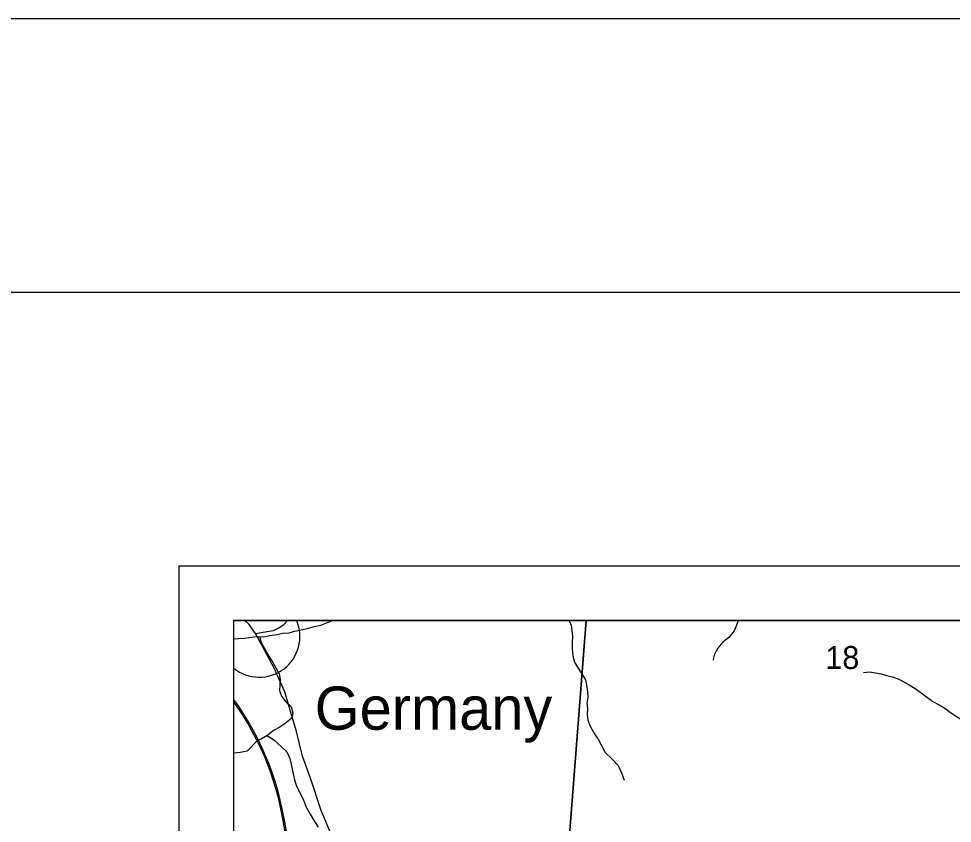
# Model space of a CAD drawing. Extents: x 0 to 40.8, y 0 to 22.
# Drawn here: x 1.707 to 3.414, y 20.53 to 22 of the extents above; entities that cross this region are included whole.
import ezdxf

# ---------------------------------------------------------------- set-up
doc = ezdxf.new("R2010")
doc.units = 0
for name, color, linetype in [('Default', 7, 'Continuous'), ('GM_X_County_Road', 7, 'Continuous'), ('GM_X_Minor_River', 7, 'Continuous'), ('GM_X_Rail_Line', 7, 'Continuous'), ('GM_X_Rail_Line_Text', 7, 'Continuous'), ('GM_X_Section_Text', 7, 'Continuous'), ('GM_X_Unincorporated_Location', 7, 'Continuous'), ('GM_X_Unincorporated_Text', 7, 'Continuous'), ('SH_Border', 7, 'Continuous'), ('SH_Cut_Line', 7, 'Continuous'), ('SH_Data', 7, 'Continuous')]:
    doc.layers.add(name, color=color, linetype=linetype)

msp = doc.modelspace()

# ---------------------------------------------------------------- linework, layer by layer
at = {"layer": 'Default'}
msp.add_lwpolyline([(3.6829, 20.9), (2.1, 20.9), (2.1, 17.4153), (2.4594, 17.3966), (2.8463, 17.3693), (2.8484, 17.3691), (3.1244, 17.3534), (3.4481, 17.3334), (3.5638, 19.132), (3.5742, 19.2945), (3.575, 19.3064), (3.6386, 20.2396), (3.6672, 20.5588), (3.6703, 20.6733)], close=True, dxfattribs=at)
at = {"layer": 'GM_X_County_Road'}
for points in [[(2.7446, 20.9), (2.1, 20.9), (2.1, 20.4303), (2.7045, 20.3832)], [(3.6903, 20.9), (2.7446, 20.9), (2.7045, 20.3832), (3.6475, 20.2502)]]:
    msp.add_lwpolyline(points, close=True, dxfattribs=at)
for points in [[(2.279, 20.5082), (2.2602, 20.5531), (2.2408, 20.6105), (2.2258, 20.6523), (2.215, 20.6972), (2.2026, 20.7383), (2.1933, 20.7698), (2.1741, 20.8132), (2.1516, 20.8551), (2.1399, 20.8768), (2.1282, 20.8928), (2.1204, 20.9)], [(2.1399, 20.8768), (2.1574, 20.8795), (2.1729, 20.8822), (2.1813, 20.886), (2.1915, 20.8932), (2.1982, 20.9)]]:
    msp.add_lwpolyline(points, dxfattribs=at)
at = {"layer": 'GM_X_Minor_River'}
for points in [[(2.1, 20.8667), (2.1089, 20.8673), (2.1199, 20.8678), (2.1328, 20.8698), (2.143, 20.871), (2.1544, 20.8703), (2.1662, 20.8727), (2.1795, 20.8746), (2.1898, 20.877), (2.2016, 20.8775), (2.2111, 20.881), (2.2233, 20.8833), (2.2347, 20.8857), (2.2469, 20.8892), (2.2595, 20.8919), (2.2714, 20.8969), (2.2798, 20.9)], [(2.7128, 20.9), (2.7168, 20.8921), (2.718, 20.8815), (2.7196, 20.8716), (2.719, 20.8602), (2.7187, 20.8485), (2.7199, 20.8359), (2.7234, 20.8244), (2.7284, 20.8148), (2.7364, 20.8029), (2.743, 20.7917), (2.7457, 20.7791), (2.7469, 20.7696), (2.7474, 20.7601), (2.7456, 20.7491), (2.7469, 20.7396), (2.7463, 20.729), (2.7475, 20.718), (2.7518, 20.7072), (2.7587, 20.6953), (2.7648, 20.6856), (2.766, 20.6849)], [(3.0223, 20.9), (3.0191, 20.8915), (3.015, 20.8814), (3.0052, 20.8695), (2.9944, 20.861), (2.9854, 20.8495), (2.9791, 20.839), (2.9765, 20.8292), (2.9765, 20.8281)], [(2.147, 20.8708), (2.15, 20.8598), (2.1565, 20.849), (2.1627, 20.8383), (2.1714, 20.8236), (2.1768, 20.8136), (2.1833, 20.8028), (2.185, 20.7925), (2.1843, 20.7823), (2.1841, 20.7721), (2.1876, 20.7621), (2.1953, 20.7517), (2.2053, 20.7427), (2.2084, 20.7316), (2.2066, 20.7218), (2.1942, 20.7119), (2.1842, 20.7053), (2.1731, 20.6991), (2.1622, 20.6907), (2.1507, 20.6842), (2.1434, 20.6809)], [(3.2517, 20.805), (3.2623, 20.8063), (3.2737, 20.8045), (3.2835, 20.8031), (3.2936, 20.7998), (3.3045, 20.7972), (3.3151, 20.7939), (3.3278, 20.7871), (3.3382, 20.7811), (3.3479, 20.7748), (3.3576, 20.7674), (3.3683, 20.7595), (3.3784, 20.752), (3.39, 20.7464), (3.4, 20.7401), (3.4108, 20.7322), (3.4209, 20.7255), (3.4324, 20.718), (3.4424, 20.7094), (3.4539, 20.7004), (3.4647, 20.691), (3.4747, 20.6824), (3.5442, 20.618)], [(2.1601, 20.6895), (2.1645, 20.6885), (2.1743, 20.6814), (2.1877, 20.6697), (2.197, 20.6601), (2.2025, 20.6482), (2.2049, 20.6379), (2.2077, 20.6253), (2.2112, 20.6089), (2.2144, 20.5994), (2.2276, 20.5718), (2.2326, 20.5592), (2.24, 20.5465), (2.248, 20.533), (2.2547, 20.5227)], [(2.1, 20.6586), (2.1121, 20.6595), (2.125, 20.6622), (2.1434, 20.6809)], [(2.766, 20.6849), (2.779, 20.6592), (2.792, 20.6472), (2.8028, 20.6352), (2.809, 20.6222), (2.8137, 20.6088)]]:
    msp.add_lwpolyline(points, dxfattribs=at)
at = {"layer": 'GM_X_Rail_Line'}
for points in [[(2.1972, 20.5111), (2.1932, 20.5352), (2.1894, 20.5534), (2.1853, 20.5718), (2.1811, 20.5876), (2.1757, 20.6058), (2.1696, 20.6243), (2.164, 20.6391), (2.1583, 20.6531), (2.1517, 20.668), (2.144, 20.684), (2.1361, 20.6988), (2.1278, 20.714), (2.118, 20.7298), (2.1086, 20.7442), (2.1, 20.7564)], [(2.1948, 20.5107), (2.1908, 20.5348), (2.187, 20.5529), (2.183, 20.5712), (2.1788, 20.587), (2.1734, 20.6051), (2.1673, 20.6235), (2.1617, 20.6383), (2.1561, 20.6522), (2.1495, 20.667), (2.1418, 20.683), (2.134, 20.6976), (2.1257, 20.7128), (2.1159, 20.7285), (2.1066, 20.7428), (2.1, 20.7522)]]:
    msp.add_lwpolyline(points, dxfattribs=at)
at = {"layer": 'GM_X_Rail_Line_Text'}
msp.add_lwpolyline([(2.2153, 20.9), (2.1, 20.9), (2.1, 20.8133)], dxfattribs=at)
msp.add_arc((2.1468, 20.8711), 0.0744, 231.0594, 22.8298, dxfattribs=at)
at = {"layer": 'GM_X_Unincorporated_Location'}
msp.add_line((2.1468, 20.8711), (2.1468, 20.8711), dxfattribs=at)
at = {"layer": 'SH_Border'}
msp.add_lwpolyline([(1.5, 21.5), (33.5, 21.5), (33.5, 0.5), (1.5, 0.5)], close=True, dxfattribs=at)
at = {"layer": 'SH_Cut_Line'}
for points in [[(0, 0), (34, 0), (34, 22), (0, 22)], [(7.7204, 20.9), (2.1, 20.9), (2.1, 17.4153), (2.4594, 17.3966), (2.8463, 17.3693), (2.8484, 17.3691), (3.1244, 17.3534), (3.4481, 17.3334), (4.5348, 17.2687), (4.8294, 17.2493), (5.3407, 17.2146), (5.6278, 17.197), (6.1785, 17.166), (6.9172, 17.1197), (7.4495, 17.0841), (7.4798, 17.5479), (7.4963, 17.9476), (7.5246, 18.2047), (7.5789, 18.8336), (7.595, 19.0259), (7.6007, 19.1025), (7.6007, 19.1071), (7.6192, 19.376), (7.7055, 20.511)]]:
    msp.add_lwpolyline(points, close=True, dxfattribs=at)
at = {"layer": 'SH_Data'}
for p, q in [((2, 21), (9, 21)), ((2, 21), (2, 14)), ((2.1, 20.9), (2.1, 14.1)), ((2.1, 20.9), (8.9, 20.9))]:
    msp.add_line(p, q, dxfattribs=at)

# ---------------------------------------------------------------- texts
at = {"layer": 'GM_X_Section_Text'}
msp.add_text('18', height=0.04186, rotation=0, dxfattribs=at).set_placement((3.1816, 20.8117))
at = {"layer": 'GM_X_Unincorporated_Text'}
msp.add_text('Germany', height=0.07898, rotation=0, dxfattribs=at).set_placement((2.2482, 20.7007))

doc.saveas('drawing.dxf')
